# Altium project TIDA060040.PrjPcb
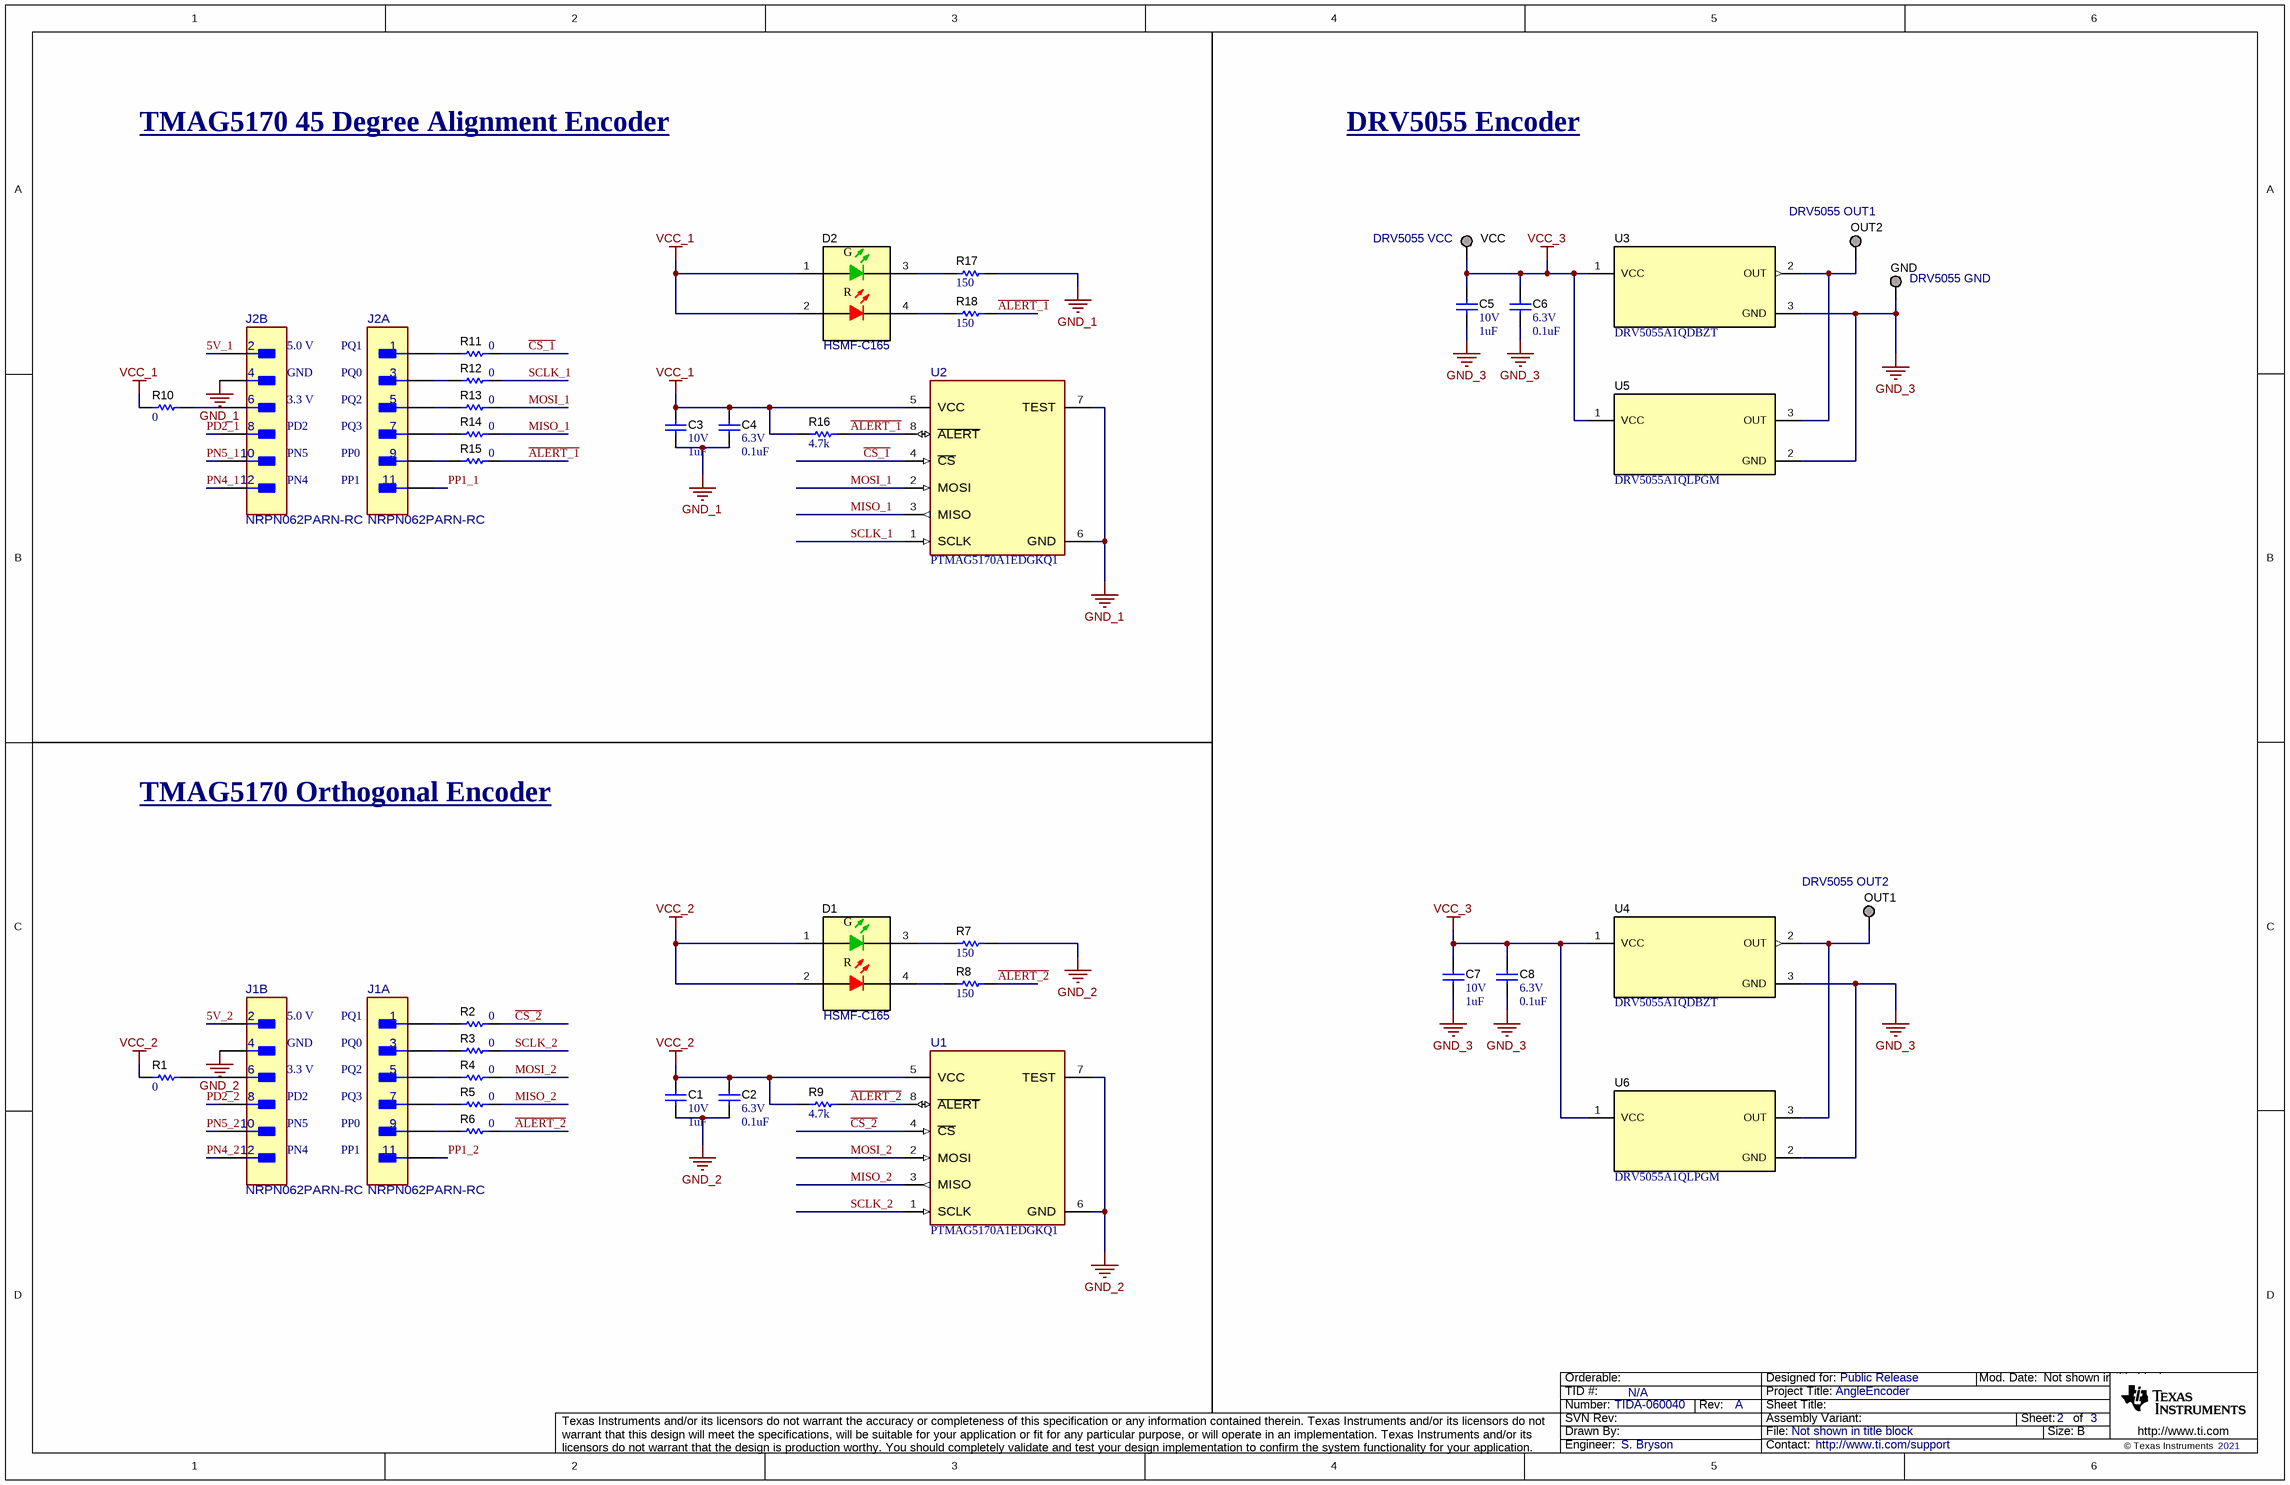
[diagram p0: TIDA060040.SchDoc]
CopyrightYear: 2021; PCB_Layout: S. Bryson; PCB_Rev: A; PRJ_Customer: Public Release; PRJ_Engineer: S. Bryson; PRJ_Number: TIDA-060040; PRJ_Title: AngleEncoder; SCH_Rev: A; TechSupport: http://www.ti.com/support; TID: N/A
2 sheets, 50 parts. Net scope: global (net labels, ports and power ports of the same name join across sheets).
Board file: TIDA060040.PcbDoc
Sheets:
  TIDA060040.SchDoc
  TIDA060040_HW.SchDoc

## Sheet TIDA060040.SchDoc
size 431 x 279 mm; Date: Not shown in title block; ApprovedBy: Not shown in title block; CheckedBy: Not shown in title block; Author: Not shown in title block; CompanyName: Not shown in title block; Engineer: Not shown in title block; Organization: Not shown in title block; Address1: Not shown in title block; Address2: Not shown in title block; Address3: Not shown in title block; Address4: Not shown in title block; DocumentNumber: 2; Revision: Use project parameter SCH_Rev; SheetNumber: 2; SheetTotal: 3; PageSetup: Record=PageOptions¦CenterHorizontal=True¦CenterVertical=True¦PrintScale=1.00¦XCorrection=1.00¦YCorrection=1.00¦PrintKind=0¦BorderSize=5000000¦LeftOffset=0¦BottomOffset=0¦Orientation=2¦PaperLength=1000¦PaperWidth=1000¦Scale=100¦PaperSource=15¦PrintQuality=600¦MediaType=1¦DitherType=10¦PaperKind=Letter¦PrintScaleMode=1

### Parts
C1  VDC_V: 10V  ValueDisplayed: 1uF  [0201L]  (hidden comment: CL03A105MP3NSNC)
C2  VDC_V: 6.3V  ValueDisplayed: 0.1uF  [0201_033L]  (hidden comment: GRM033R60J104KE19D)
C3  VDC_V: 10V  ValueDisplayed: 1uF  [0201L]  (hidden comment: CL03A105MP3NSNC)
C4  VDC_V: 6.3V  ValueDisplayed: 0.1uF  [0201_033L]  (hidden comment: GRM033R60J104KE19D)
C5  VDC_V: 10V  ValueDisplayed: 1uF  [0201L]  (hidden comment: CL03A105MP3NSNC)
C6  VDC_V: 6.3V  ValueDisplayed: 0.1uF  [0201_033L]  (hidden comment: GRM033R60J104KE19D)
C7  VDC_V: 10V  ValueDisplayed: 1uF  [0201L]  (hidden comment: CL03A105MP3NSNC)
C8  VDC_V: 6.3V  ValueDisplayed: 0.1uF  [0201_033L]  (hidden comment: GRM033R60J104KE19D)
D1  HSMF-C165  [HSMF-C165_RG]
D2  HSMF-C165  [HSMF-C165_RG]
GND  DRV5055 GND  [Keystone_5017]  (no BOM)
J1  NRPN062PARN-RC  [FP-NRPN062PARN-RC_HDR12-MFG]  (parts A,B of 2)
J2  NRPN062PARN-RC  [FP-NRPN062PARN-RC_HDR12-MFG]  (parts A,B of 2)
OUT1  DRV5055 OUT2  [Keystone_5017]  (no BOM)
OUT2  DRV5055 OUT1  [Keystone_5017]  (no BOM)
R1  ValueDisplayed: 0  [0603M]  (hidden comment: CRCW06030000Z0EA)
R2  ValueDisplayed: 0  [0201L]  (hidden comment: CRCW02010000Z0ED)
R3  ValueDisplayed: 0  [0201L]  (hidden comment: CRCW02010000Z0ED)
R4  ValueDisplayed: 0  [0201L]  (hidden comment: CRCW02010000Z0ED)
R5  ValueDisplayed: 0  [0201L]  (hidden comment: CRCW02010000Z0ED)
R6  ValueDisplayed: 0  [0201L]  (hidden comment: CRCW02010000Z0ED)
R7  ValueDisplayed: 150  [0201L]  (hidden comment: RC0201JR-07150RL)
R8  ValueDisplayed: 150  [0201L]  (hidden comment: RC0201JR-07150RL)
R9  ValueDisplayed: 4.7k  [0201]  (hidden comment: RC0201JR-7D4K7L)
R10  ValueDisplayed: 0  [0603M]  (hidden comment: CRCW06030000Z0EA)
R11  ValueDisplayed: 0  [0201L]  (hidden comment: CRCW02010000Z0ED)
R12  ValueDisplayed: 0  [0201L]  (hidden comment: CRCW02010000Z0ED)
R13  ValueDisplayed: 0  [0201L]  (hidden comment: CRCW02010000Z0ED)
R14  ValueDisplayed: 0  [0201L]  (hidden comment: CRCW02010000Z0ED)
R15  ValueDisplayed: 0  [0201L]  (hidden comment: CRCW02010000Z0ED)
R16  ValueDisplayed: 4.7k  [0201L]  (hidden comment: CRCW02010000Z0ED)
R17  ValueDisplayed: 150  [0201L]  (hidden comment: RC0201JR-07150RL)
R18  ValueDisplayed: 150  [0201L]  (hidden comment: RC0201JR-07150RL)
U1  PTMAG5170A1EDGKQ1  [DGK0008A-IPC_C]
U2  PTMAG5170A1EDGKQ1  [DGK0008A-IPC_C]
U3  DRV5055A1QDBZT  [DBZ0003A_N]
U4  DRV5055A1QDBZT  [DBZ0003A_N]
U5  DRV5055A1QLPGM  [LPG0003A]
U6  DRV5055A1QLPGM  [LPG0003A]
VCC  DRV5055 VCC  [Keystone_5017]  (no BOM)

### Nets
GND_1: C3.1 C4.2 J2.4 R17.2 U2.6(GND) U2.7(TEST)
GND_2: C1.1 C2.2 J1.4 R7.2 U1.6(GND) U1.7(TEST)
GND_3: C5.1 C6.2 C7.1 C8.2 GND.1 U3.3(GND) U4.3(GND) U5.2(GND) U6.2(GND)
VCC_1: C3.2 C4.1 D2.1(A) D2.2(A) R10.1 R16.2 U2.5(VCC)
VCC_2: C1.2 C2.1 D1.1(A) D1.2(A) R1.1 R9.2 U1.5(VCC)
VCC_3: C5.2 C6.1 C7.2 C8.1 U3.1(VCC) U4.1(VCC) U5.1(VCC) U6.1(VCC) VCC.1
5V_1: J2.2
5V_2: J1.2
~{ALERT_1}: R15.2 R16.1 R18.2 U2.8(~{ALERT})
~{ALERT_2}: R6.2 R8.2 R9.1 U1.8(~{ALERT})
~{CS_1}: R11.2 U2.4(~{CS})
~{CS_2}: R2.2 U1.4(~{CS})
MISO_1: R14.2 U2.3(MISO)
MISO_2: R5.2 U1.3(MISO)
MOSI_1: R13.2 U2.2(MOSI)
MOSI_2: R4.2 U1.2(MOSI)
PD2_1: J2.8
PD2_2: J1.8
PN4_1: J2.12
PN4_2: J1.12
PN5_1: J2.10
PN5_2: J1.10
PP1_1: J2.11
PP1_2: J1.11
SCLK_1: R12.2 U2.1(SCLK)
SCLK_2: R3.2 U1.1(SCLK)
NetD1_3: D1.3(K) R7.1
NetD1_4: D1.4(K) R8.1
NetD2_3: D2.3(K) R17.1
NetD2_4: D2.4(K) R18.1
NetJ1_1: J1.1 R2.1
NetJ1_3: J1.3 R3.1
NetJ1_5: J1.5 R4.1
NetJ1_6: J1.6 R1.2
NetJ1_7: J1.7 R5.1
NetJ1_9: J1.9 R6.1
NetJ2_1: J2.1 R11.1
NetJ2_3: J2.3 R12.1
NetJ2_5: J2.5 R13.1
NetJ2_6: J2.6 R10.2
NetJ2_7: J2.7 R14.1
NetJ2_9: J2.9 R15.1
NetOUT1_1: OUT1.1 U4.2(OUT) U6.3(OUT)
NetOUT2_1: OUT2.1 U3.2(OUT) U5.3(OUT)

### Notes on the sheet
- TMAG5170 45 Degree Alignment Encoder
- DRV5055 Encoder
- (near J2) 5.0 V
- (near J2) PQ1
- (near J2) 3.3 V
- (near J2) PD2
- (near J2) GND
- (near J2) PQ3
- (near J2) PQ2
- (near J2) PQ0
- (near J2) PN5
- (near J2) PN4
- (near J2) PP1
- (near J2) PP0
- TMAG5170 Orthogonal Encoder
- (near J1) 5.0 V
- (near J1) PQ1
- (near J1) 3.3 V
- (near J1) PD2
- (near J1) GND
- (near J1) PQ3
- (near J1) PQ2
- (near J1) PQ0
- (near J1) PN5
- (near J1) PN4
- (near J1) PP1
- (near J1) PP0

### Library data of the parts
C1 C3 C5 C7 = CMP-0009656-3: CAP, CERM, 1 uF, 10 V, +/- 20%, X5R, 0201; Manufacturer: Samsung Electro-Mechanics; TaMin_C: -55°C; Polarized: N; SizeAreaWB_mm2: 2.08; Value1: Unknown; U/M: EA; Value: 1uF; TaMax_C: 85°C; SizeZ_mm: 0.26; SizeX_mm: 0.6; SizeY_mm: 0.3; Cap_Case: 0201; SizeArea_mm2: 0.18; Cap_F: 1µF; AEC Category: Q200
C2 C4 C6 C8 = CMP-0009690-3: CAP, CERM, 0.1 uF, 6.3 V, +/- 10%, X5R, 0201; Manufacturer: MuRata; TaMin_C: -55°C; Polarized: N; SizeAreaWB_mm2: 2.08; Value1: Unknown; U/M: EA; Value: 0.1uF; TaMax_C: 85°C; SizeZ_mm: 0.33; SizeX_mm: 0.6; SizeY_mm: 0.3; Cap_Case: 0201; SizeArea_mm2: 0.18; Cap_F: 100nF; AEC Category: Q200
D1 D2 = CMP-0002934-2: LED, Rg, SMD; Manufacturer: Avago; Io_A: 20mA; Vr_V: 5V; Tjmax_C: 85°C; Value1: W; U/M: EA; Angle: 120; Ir_A: 100µA; Vf_V: 2.2V; LuminousIntensity_IV: 20
GND OUT1 OUT2 VCC = CMP-0078225-1: PC Test Point, SMT; PartNumber: 5017; Manufacturer: Keystone
J1 J2 = CMP-0090321-1: Manufacturer: Sullins Connector Solutions; Voltage_V: 150V; Row_Count: 2; DUT-Pitch_mm: 2mm; Conn Gender: Male; AEC Qualified: No; SizeZ_mm: 4.2mm; Conn Orientation: Right Angle; ContactFinish: Gold; Current_A: 2A
R1 R10 = CMP-0025697-4: RES, 0, 5%, 0.1 W, AEC-Q200 Grade 0, 0603; Manufacturer: Vishay-Dale; Power_W: 100mW; TempCo: 200 ppm/C; Value_Code: 0000; Value: 0; EIA_Code: E24; SizeX_mm: 1.6; SizeY_mm: 0.8; SizeZ_mm: 1; Value2: 0.1W; SizeArea_mm2: 1.28; AEC Qualified: Y; VDC_V: 75V; AEC Category: Q200
R2-R6 R11-R15 = CMP-0027008-4: RES, 0, 5%, 0.05 W, 0201; Manufacturer: Vishay-Dale; Power_W: 50mW; TempCo: ppm/C; Value_Code: 0000; Value: 0; EIA_Code: E24; SizeX_mm: 0.6; SizeY_mm: 0.3; SizeZ_mm: 0.26; Value2: 0.05W; SizeArea_mm2: 0.18; AEC Qualified: N; AEC Category: Q200
R7 R8 R17 R18 = CMP-0027035-1: RES, 150, 5%, 0.05 W, 0201; Manufacturer: Yageo America; Power_W: 50mW; TempCo: 200 ppm/C; Value_Code: 150R; U/M: EA; Value: 150; EIA_Code: E24; SizeX_mm: 0.6; SizeY_mm: 0.3; SizeZ_mm: 0.26; Value2: 0.05W; SizeArea_mm2: 0.18; AEC Qualified: N; VDC_V: 25V; AEC Category: Q200
R9 = CMP-0027242-1: RES, 4.7 k, 5%, 0.05 W, 0201; Manufacturer: Yageo America; Power_W: 50mW; TempCo: 200 ppm/C; Value_Code: 4k70; U/M: EA; Value: 4.7k; EIA_Code: E24; SizeX_mm: 0.6; SizeY_mm: 0.3; SizeZ_mm: 0.26; Value2: 0.05W; SizeArea_mm2: 0.18; AEC Qualified: N; VDC_V: 25V; AEC Category: Q200
R16 = CMP-0027242-1: RES, 4.7 k, 5%, 0.05 W, 0201; Manufacturer: Yageo America; PartNumber: RC0201JR-7D4K7L; Alternate PartNumber: ERA-1AEB472C; Power_W: 50mW; TempCo: 200 ppm/C; Value_Code: 4k70; U/M: EA; Value: 4.7k; EIA_Code: E24; SizeX_mm: 0.6; SizeY_mm: 0.3; SizeZ_mm: 0.26; Value2: 0.05W; SizeArea_mm2: 0.18; AEC Qualified: N; VDC_V: 25V; AEC Category: Q200
U1 U2 = CMP-0091328-1: Automotive, 3D high-precision linear Hall effect sensor with SPI bus interface 8-VSSOP -40 to 150; Manufacturer: Texas Instruments; Standoff Height: 0.05mm; TJmax_C: +170°C; TaMin_C: -40°C; AEC Grade: Grade 0; Max Supply Voltage: 5.5V; Min Supply Voltage: 2.3V; TaMax_C: +150°C; SizeZ_mm: 1.1mm; AEC Qualified: Yes; Operating Supply Current: 3.4mA
U3 U4 = CMP-0081694-1: High Accuracy 3.3 V or 5 V Ratiometric Bipolar Hall Effect Sensor Family, DBZ0003A (SOT-23-3); Alternate PartNumber: DRV5055A1QDBZR; Alternate Manufacturer: Texas Instruments; SizeAreaWB_mm2: 14; Rating: Catalog; SizeZ_mm: 1.12; SizeX_mm: 2.5; SizeY_mm: 3; SizeArea_mm2: 7.5; CompType: IC; AEC Qualified: N; AEC Category: Q200
U5 U6 = CMP-0081697-1: High Accuracy 3.3 V or 5 V Ratiometric Bipolar Hall Effect Sensor Family, LPG0003A (TO-92-3); Alternate Manufacturer: Texas Instruments; SizeAreaWB_mm2: 20.75; Rating: Catalog; SizeZ_mm: 5.05; SizeX_mm: 4; SizeY_mm: 3.15; SizeArea_mm2: 12.6; CompType: IC; AEC Qualified: N; AEC Category: Q200

## Sheet TIDA060040_HW.SchDoc
size 431 x 279 mm; Date: Not shown in title block; ApprovedBy: Not shown in title block; CheckedBy: Not shown in title block; Author: Not shown in title block; CompanyName: Not shown in title block; Engineer: Not shown in title block; Organization: Not shown in title block; Address1: Not shown in title block; Address2: Not shown in title block; Address3: Not shown in title block; Address4: Not shown in title block; DocumentNumber: 3; Revision: Use project parameter SCH_Rev; SheetNumber: 3; SheetTotal: 3; PageSetup: Record=PageOptions¦CenterHorizontal=True¦CenterVertical=True¦PrintScale=1.00¦XCorrection=1.00¦YCorrection=1.00¦PrintKind=0¦BorderSize=5000000¦LeftOffset=0¦BottomOffset=0¦Orientation=2¦PaperLength=1000¦PaperWidth=1000¦Scale=100¦PaperSource=15¦PrintQuality=600¦MediaType=1¦DitherType=10¦PaperKind=Letter¦PrintScaleMode=1
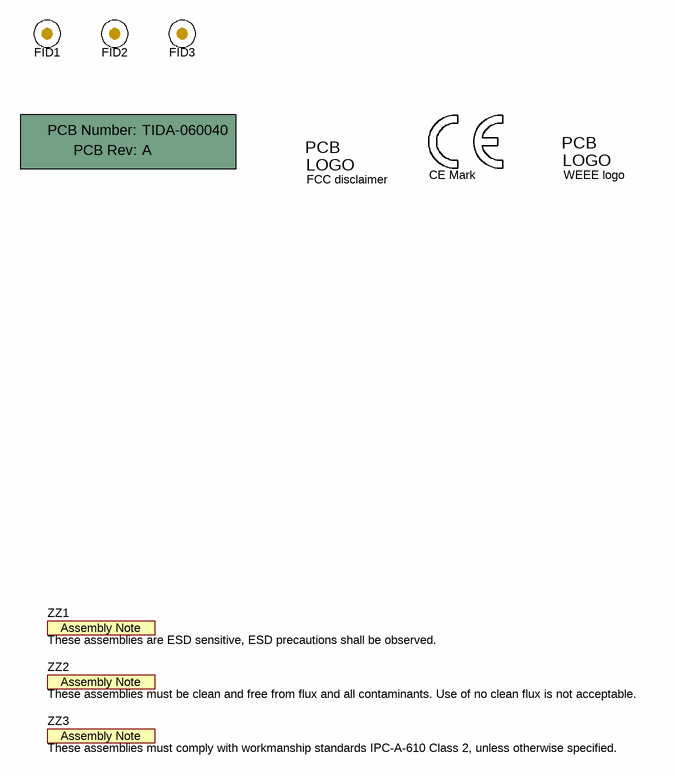
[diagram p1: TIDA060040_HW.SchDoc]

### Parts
!PCB1  Printed Circuit Board  (value not drawn)  (mechanical)
FID1  Fiducial  [Fiducial10-20]  (value not drawn)
FID2  Fiducial  [Fiducial10-20]  (value not drawn)
FID3  Fiducial  [Fiducial10-20]  (value not drawn)
Logo2  CE Mark  [CE_Mark_5mm]  (no BOM)
Logo4  WEEE logo  [WEEE_Minimum]  (no BOM)
Logo?  FCC disclaimer  [FCC_disclaimer]  (no BOM)
ZZ1  These assemblies are ESD sensitive, ESD precautions shall be observed.  [AssemblyNote]  (no BOM)
ZZ2  These assemblies must be clean and free from flux and all contaminants. Use of no clean flux is not acceptable.  [AssemblyNote]  (no BOM)
ZZ3  These assemblies must comply with workmanship standards IPC-A-610 Class 2, unless otherwise specified.  [AssemblyNote]  (no BOM)

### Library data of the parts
!PCB1 = CMP-0003618-2: Manufacturer: Any; PartNumber: TIDA-060040
FID1-FID3 = CMP-0077181-1: Fiducial mark.  There is nothing to buy or mount.
Logo2 = CMP-0074844-1: SymbolCreator: a0412235
Logo4 = CMP-0074769-1
Logo? = CMP-0074847-1: FCC_disclaimer; Library Reference: Logo
ZZ1 = CMP-0077236-1
ZZ2 = CMP-0077237-1
ZZ3 = CMP-0077238-1

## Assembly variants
001: not fitted FID1 FID2 FID3 U5 U6
LPG DRV5055: not fitted FID1 FID2 FID3 U3 U4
